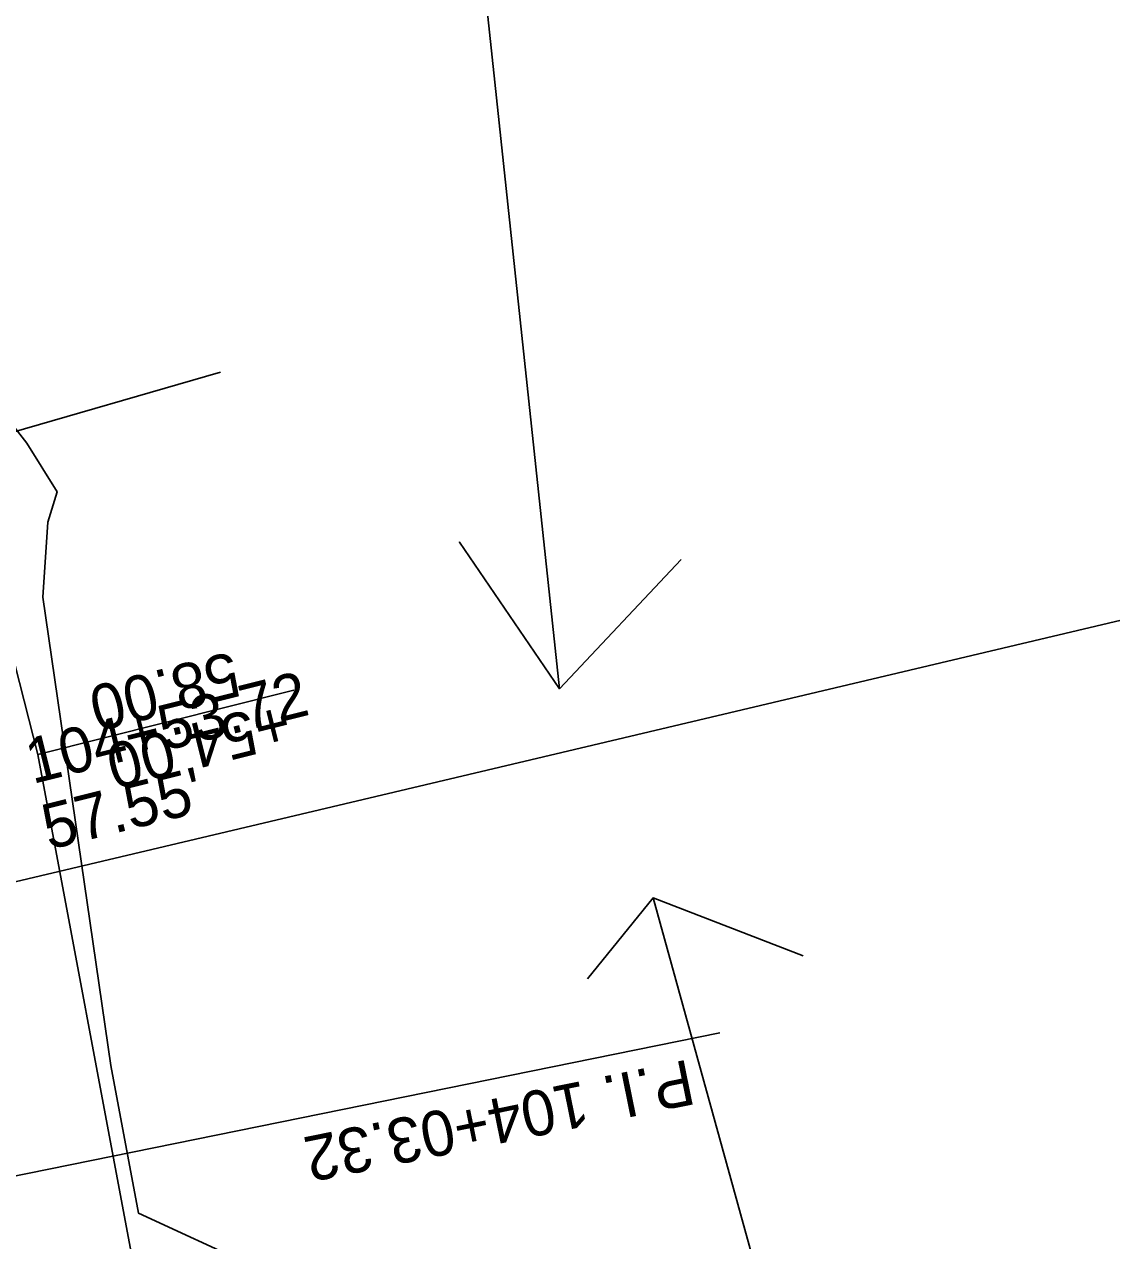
# Model space of a CAD drawing. Extents: x -70 to 701944, y -4 to 666871.
# Drawn here: x 668432 to 668576.2, y 653666.5 to 653827.8 of the extents above; entities that cross this region are included whole.
import ezdxf

# ---------------------------------------------------------------- set-up
doc = ezdxf.new("R2010")
doc.units = 0
for name, color, linetype in [('R_Detour', 7, 'Continuous'), ('R_Horz Alg Annot', 7, 'Continuous'), ('R_No Plot', 7, 'Continuous'), ('R_ROW', 7, 'Continuous'), ('R_ROW Annot', 7, 'Continuous'), ('T_Drafting', 7, 'Continuous')]:
    doc.layers.add(name, color=color, linetype=linetype)

msp = doc.modelspace()

# ---------------------------------------------------------------- linework, layer by layer
at = {"layer": 'R_Detour'}
for p, q in [((668458.01, 653781.68), (668367.13, 653755.51)), ((668684.78, 653774.18), (668381.07, 653702.32)), ((668515.38, 653711.94), (668535.32, 653704.27))]:
    msp.add_line(p, q, dxfattribs=at)
for points in [[(668486.62, 653893.19), (668502.98, 653739.7), (668489.69, 653759.14), (668502.98, 653739.7), (668519.13, 653756.84)], [(668564.98, 653532.61), (668515.38, 653711.94), (668506.69, 653701.2)]]:
    msp.add_lwpolyline(points, dxfattribs=at)
at = {"layer": 'R_Horz Alg Annot'}
msp.add_lwpolyline([(668399.04, 653668.62), (668524.26, 653694.06)], dxfattribs=at)
at = {"layer": 'R_ROW'}
msp.add_lwpolyline([(668379.35, 655858.1), (668375.98, 655777.07), (668370.36, 655679.23), (668386.89, 655520.28), (668407.12, 655376.16), (668401.28, 655337.39), (668367.53, 655300.94), (668336.13, 654741.8), (668319.02, 654252.06), (668346.25, 654066.79), (668364.92, 653986.53), (668401.01, 653983.18), (668425.78, 653872.16), (668398.63, 653868.03), (668433.79, 653730.98), (668450.99, 653639.16), (668466.96, 653535.35), (668502.13, 653505.82)], dxfattribs=at)
at = {"layer": 'R_ROW Annot'}
msp.add_lwpolyline([(668433.79, 653730.98), (668467.74, 653739.49)], dxfattribs=at)
at = {"layer": 'T_Drafting'}
msp.add_lwpolyline([(668422.16, 653785.25), (668432.31, 653772.29), (668436.33, 653765.81), (668435.11, 653761.78), (668434.42, 653751.83), (668443.45, 653689.73), (668447.13, 653670.11), (668447.13, 653670.11), (668462.45, 653663.06), (668470.41, 653656.93), (668472.25, 653652.03), (668476.84, 653622.3), (668478.07, 653597.17), (668473.17, 653571.43), (668472.25, 653560.39), (668487.54, 653549.24), (668510.55, 653544.44), (668527.49, 653553.75), (668549.2, 653563.7), (668579.18, 653601.19)], dxfattribs=at)

# ---------------------------------------------------------------- texts
at = {"layer": 'R_Horz Alg Annot'}
msp.add_text('P.I. 104+03.32', height=6, rotation=191.4823, dxfattribs=at).set_placement((668520.09, 653690.55))
at = {"layer": 'R_No Plot'}
for s, p in [('104+53.72 ', (668433.06, 653727.04)), ("57.55' ", (668435.24, 653718.31))]:
    msp.add_text(s, height=6, rotation=14.0481, dxfattribs=at).set_placement(p)
at = {"layer": 'R_ROW Annot'}
for s, p in [('58.00', (668459.64, 653744.68)), ('+54.00', (668466.44, 653738.13))]:
    msp.add_text(s, height=6, rotation=194.0622, dxfattribs=at).set_placement(p)

doc.saveas('drawing.dxf')
